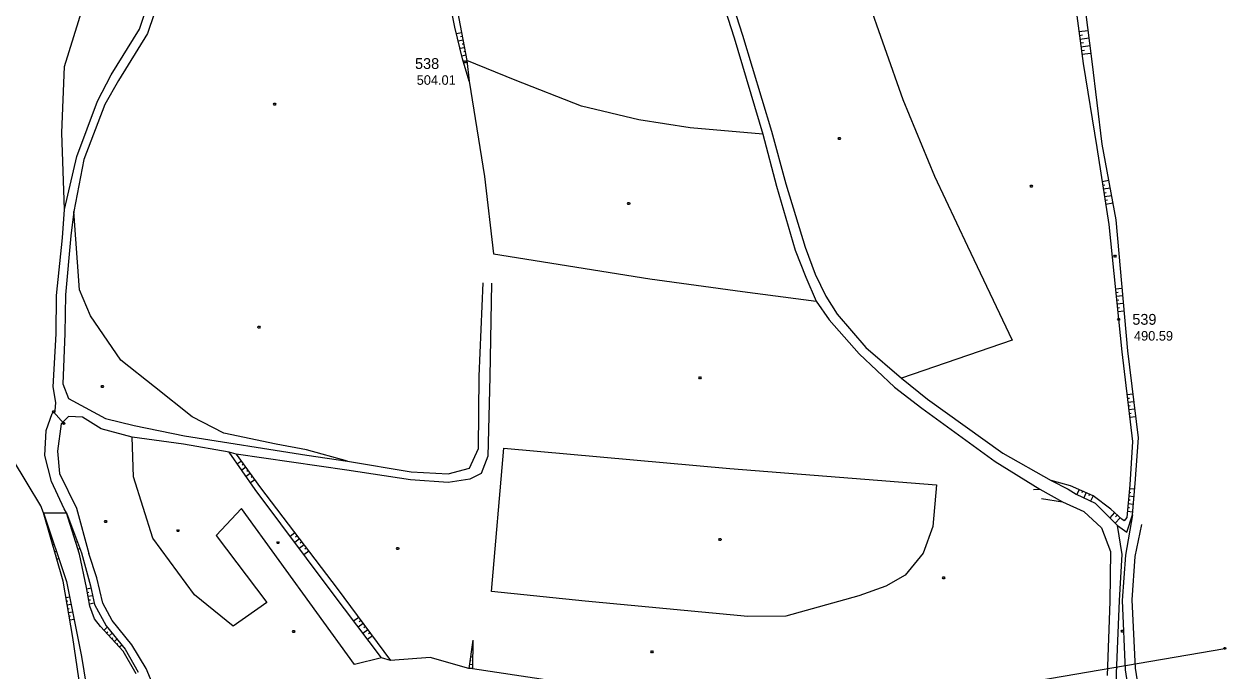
# Model space of a CAD drawing. Extents: x -664960 to -662754, y -993849 to -991145.
# Drawn here: x -663131.8 to -662753.9, y -992572.6 to -992369.4 of the extents above; entities that cross this region are included whole.
import ezdxf

# ---------------------------------------------------------------- set-up
doc = ezdxf.new("R2010")
doc.units = 0
for name, color, linetype in [('Vrstva 1', 7, 'Continuous'), ('Vrstva 13', 7, 'Continuous'), ('Vrstva 24', 7, 'Continuous'), ('Vrstva 27', 7, 'Continuous'), ('Vrstva 37', 7, 'Continuous'), ('Vrstva 57', 7, 'Continuous'), ('Vrstva 63', 7, 'Continuous'), ('Vrstva 8', 7, 'Continuous')]:
    doc.layers.add(name, color=color, linetype=linetype)

msp = doc.modelspace()

# ---------------------------------------------------------------- linework, layer by layer
at = {"layer": 'Vrstva 13'}
for points in [[(-663052.795, -992394.208), (-663052.615, -992394.508), (-663052.795, -992394.808), (-663053.155, -992394.808), (-663053.335, -992394.508), (-663053.155, -992394.208), (-663052.795, -992394.208)], [(-662875.272, -992405.031), (-662875.092, -992405.331), (-662875.272, -992405.631), (-662875.632, -992405.631), (-662875.812, -992405.331), (-662875.632, -992405.031), (-662875.272, -992405.031)], [(-662814.915, -992419.966), (-662814.735, -992420.266), (-662814.915, -992420.566), (-662815.275, -992420.566), (-662815.455, -992420.266), (-662815.275, -992419.966), (-662814.915, -992419.966)], [(-662941.47, -992425.441), (-662941.29, -992425.741), (-662941.47, -992426.041), (-662941.83, -992426.041), (-662942.01, -992425.741), (-662941.83, -992425.441), (-662941.47, -992425.441)], [(-662788.625, -992441.988), (-662788.445, -992442.288), (-662788.625, -992442.588), (-662788.985, -992442.588), (-662789.165, -992442.288), (-662788.985, -992441.988), (-662788.625, -992441.988)], [(-663057.769, -992464.306), (-663057.589, -992464.606), (-663057.769, -992464.906), (-663058.129, -992464.906), (-663058.309, -992464.606), (-663058.129, -992464.306), (-663057.769, -992464.306)], [(-662919.079, -992480.201), (-662918.899, -992480.501), (-662919.079, -992480.801), (-662919.439, -992480.801), (-662919.619, -992480.501), (-662919.439, -992480.201), (-662919.079, -992480.201)], [(-663106.964, -992482.962), (-663106.784, -992483.262), (-663106.964, -992483.562), (-663107.324, -992483.562), (-663107.504, -992483.262), (-663107.324, -992482.962), (-663106.964, -992482.962)], [(-663105.943, -992525.375), (-663105.763, -992525.675), (-663105.943, -992525.975), (-663106.303, -992525.975), (-663106.483, -992525.675), (-663106.303, -992525.375), (-663105.943, -992525.375)], [(-663083.187, -992528.227), (-663083.007, -992528.527), (-663083.187, -992528.827), (-663083.547, -992528.827), (-663083.727, -992528.527), (-663083.547, -992528.227), (-663083.187, -992528.227)], [(-663051.779, -992531.999), (-663051.599, -992532.299), (-663051.779, -992532.599), (-663052.139, -992532.599), (-663052.319, -992532.299), (-663052.139, -992531.999), (-663051.779, -992531.999)], [(-663014.102, -992533.84), (-663013.922, -992534.14), (-663014.102, -992534.44), (-663014.462, -992534.44), (-663014.642, -992534.14), (-663014.462, -992533.84), (-663014.102, -992533.84)], [(-662912.752, -992530.978), (-662912.572, -992531.278), (-662912.752, -992531.578), (-662913.112, -992531.578), (-662913.292, -992531.278), (-662913.112, -992530.978), (-662912.752, -992530.978)], [(-663046.817, -992559.864), (-663046.637, -992560.164), (-663046.817, -992560.464), (-663047.177, -992560.464), (-663047.357, -992560.164), (-663047.177, -992559.864), (-663046.817, -992559.864)], [(-662934.169, -992566.322), (-662933.989, -992566.622), (-662934.169, -992566.922), (-662934.529, -992566.922), (-662934.709, -992566.622), (-662934.529, -992566.322), (-662934.169, -992566.322)]]:
    msp.add_lwpolyline(points, dxfattribs=at)
at = {"layer": 'Vrstva 24'}
msp.add_line((-663122.48, -992491.2), (-663119.31, -992494.83), dxfattribs=at)
for points in [[(-663122.136, -992491.138), (-663122.243, -992491.471), (-663122.588, -992491.533), (-663122.824, -992491.262), (-663122.717, -992490.929), (-663122.372, -992490.867), (-663122.136, -992491.138)], [(-663118.966, -992494.768), (-663119.073, -992495.101), (-663119.418, -992495.163), (-663119.654, -992494.892), (-663119.547, -992494.559), (-663119.202, -992494.497), (-663118.966, -992494.768)]]:
    msp.add_lwpolyline(points, dxfattribs=at)
at = {"layer": 'Vrstva 27'}
for p, q in [((-662814.36, -992515.61), (-662812.41, -992515.53)), ((-662811.92, -992518.37), (-662805.32, -992519.43))]:
    msp.add_line(p, q, dxfattribs=at)
for points in [[(-662962.44, -992285.29), (-662960.53, -992287.98), (-662957.278, -992291.341), (-662954.15, -992294.72), (-662938.36, -992310.24), (-662929.08, -992320.03), (-662920.86, -992330.7), (-662912.84, -992351.32), (-662905.9, -992372.83), (-662896.75, -992402.99), (-662892.28, -992419.6), (-662886.17, -992439.46), (-662883.07, -992447.93), (-662879.65, -992454.82), (-662876.1, -992460.53), (-662867.14, -992470.96), (-662855.91, -992480.61), (-662847.69, -992487.2), (-662824.02, -992504.16), (-662808.83, -992512.81)], [(-662915.46, -992352.13), (-662908.55, -992373.66), (-662899.47, -992403.95), (-662895.23, -992420.32), (-662889.3, -992440.46), (-662885.94, -992448.86), (-662882.7, -992456.39), (-662878.63, -992462.26), (-662869.22, -992472.97), (-662858.13, -992483.47), (-662849.47, -992490.05), (-662826.45, -992506.77), (-662812.41, -992515.53), (-662805.32, -992519.43), (-662798.62, -992522.51), (-662792.97, -992527.59), (-662790.18, -992535.09), (-662790.37, -992550.8), (-662791.29, -992573.99)], [(-663118.46, -992522.94), (-663119.14, -992521.62), (-663123.2, -992513.12), (-663125.3, -992504.94), (-663124.86, -992497.07), (-663122.93, -992491.73), (-663121.97, -992490.9), (-663121.76, -992488.25), (-663122.62, -992483.39), (-663121.64, -992466.72), (-663121.59, -992454.65), (-663119.7, -992436.52), (-663119.1, -992427.6), (-663115.21, -992410.98), (-663108.68, -992393.65), (-663104.35, -992385.29), (-663095.49, -992371.02), (-663091.69, -992359.65)], [(-663088.9, -992360.19), (-663092.97, -992372.36), (-663102.14, -992387.15), (-663106.34, -992394.7), (-663113.04, -992411.93), (-663116.16, -992428.31), (-663117.11, -992435.92), (-663118.74, -992454.46), (-663119.01, -992466.58), (-663119.63, -992482.42), (-663117.8, -992487.01), (-663112.58, -992489.8), (-663106.21, -992493.25), (-663097.17, -992495.53), (-663081.3, -992498.71), (-663042.91, -992504.81), (-663030.1, -992506.69), (-663010.06, -992510.04), (-662998.46, -992510.71), (-662991.72, -992508.85), (-662988.9, -992502.7), (-662988.66, -992479.99), (-662987.44, -992450.67)], [(-662984.85, -992450.76), (-662985.33, -992480.16), (-662985.96, -992505.11), (-662988.05, -992510.57), (-662991.59, -992512.36), (-662998.47, -992513.41), (-663010.23, -992512.59), (-663030.34, -992509.54), (-663065.05, -992504.46), (-663067.25, -992503.83), (-663081.69, -992501.34), (-663097.79, -992499.15), (-663107.52, -992496.58), (-663113.36, -992492.91), (-663117.8, -992492.65), (-663120.15, -992494.99), (-663121.26, -992503.6), (-663120.65, -992510.56), (-663115.29, -992521.42), (-663111.38, -992535.68)], [(-662783.31, -992523.58), (-662785.46, -992536.18), (-662786.51, -992550.42), (-662785.54, -992572.27), (-662783.94, -992583.1)], [(-662814.02, -992628.77), (-662807.9, -992624.04), (-662800.53, -992615), (-662795.19, -992606.64), (-662791.07, -992598.2), (-662789.03, -992589.4), (-662788.34, -992581.72), (-662788.3, -992573.38), (-662787.39, -992550.45), (-662786.57, -992536.01), (-662787.99, -992526.89)], [(-662773.98, -992603.1), (-662777.38, -992600.19), (-662778.5, -992597.92), (-662779.16, -992594.44), (-662780.59, -992582.88), (-662782.36, -992571.76), (-662783.36, -992550.29), (-662782.46, -992536.59), (-662780.37, -992526.63)], [(-663018.16, -992685.44), (-663025.79, -992675.92), (-663035.27, -992659.28), (-663038.99, -992653.02), (-663043.87, -992645.7), (-663048.47, -992640.36), (-663053.15, -992637.16), (-663070.22, -992627.63), (-663076.51, -992622.16), (-663079.98, -992619.34), (-663083.32, -992614.59), (-663086.51, -992609.81), (-663087.86, -992602.34), (-663087.8, -992594.56), (-663088.03, -992588.91), (-663090.1, -992579.58), (-663093.42, -992571.81), (-663097.88, -992564.38), (-663104.09, -992556.79), (-663107.01, -992551.26), (-663108.93, -992543.34), (-663111.38, -992535.68)]]:
    msp.add_lwpolyline(points, dxfattribs=at)
at = {"layer": 'Vrstva 37'}
msp.add_lwpolyline([(-662754.07, -992565.19), (-662753.89, -992565.49), (-662754.07, -992565.79), (-662754.43, -992565.79), (-662754.61, -992565.49), (-662754.43, -992565.19), (-662754.07, -992565.19)], dxfattribs=at)
at = {"layer": 'Vrstva 57'}
msp.add_lwpolyline([(-663665.051, -992722.016), (-663550.65, -992702.35), (-663440.01, -992683.39), (-663326.32, -992663.75), (-663217.09, -992644.97), (-663109.78, -992626.53), (-662986.28, -992605.36), (-662863.82, -992584.32), (-662754.25, -992565.49)], dxfattribs=at)
at = {"layer": 'Vrstva 63'}
for p, q in [((-662800.134, -992371.749), (-662797.222, -992371.366)), ((-662994.263, -992372.117), (-662995.804, -992372.411)), ((-662993.814, -992374.475), (-662995.239, -992374.747)), ((-662994.039, -992373.296), (-662994.532, -992373.39)), ((-662799.978, -992372.939), (-662799.011, -992372.812)), ((-662799.822, -992374.128), (-662796.923, -992373.748)), ((-662799.666, -992375.318), (-662798.703, -992375.192)), ((-662993.365, -992376.832), (-662994.674, -992377.082)), ((-662993.589, -992375.654), (-662994.044, -992375.74)), ((-662993.14, -992378.011), (-662993.556, -992378.091)), ((-662799.51, -992376.508), (-662796.624, -992376.129)), ((-662799.353, -992377.698), (-662798.395, -992377.572)), ((-662799.197, -992378.888), (-662796.325, -992378.51)), ((-662992.915, -992379.19), (-662994.108, -992379.418)), ((-662792.845, -992418.803), (-662790.668, -992418.464)), ((-662792.661, -992419.989), (-662791.924, -992419.874)), ((-662792.476, -992421.175), (-662790.23, -992420.825)), ((-662792.291, -992422.36), (-662791.532, -992422.242)), ((-662792.107, -992423.546), (-662789.792, -992423.185)), ((-662791.922, -992424.732), (-662791.14, -992424.61)), ((-662791.737, -992425.917), (-662789.354, -992425.546)), ((-662788.656, -992452.524), (-662786.477, -992452.299)), ((-662788.532, -992453.718), (-662787.813, -992453.643)), ((-662788.409, -992454.911), (-662786.266, -992454.69)), ((-662788.286, -992456.105), (-662787.578, -992456.032)), ((-662788.163, -992457.299), (-662786.056, -992457.081)), ((-662788.04, -992458.492), (-662787.344, -992458.42)), ((-662787.917, -992459.686), (-662785.845, -992459.472)), ((-662785.04, -992485.745), (-662783.114, -992485.519)), ((-662784.9, -992486.936), (-662784.258, -992486.861)), ((-662784.76, -992488.128), (-662782.827, -992487.902)), ((-662784.621, -992489.32), (-662783.976, -992489.244)), ((-662784.481, -992490.512), (-662782.54, -992490.284)), ((-662784.341, -992491.704), (-662783.694, -992491.628)), ((-662784.201, -992492.896), (-662782.253, -992492.667)), ((-663063.451, -992506.681), (-663064.666, -992507.556)), ((-663062.049, -992508.629), (-663063.297, -992509.528)), ((-663062.75, -992507.655), (-663063.16, -992507.95)), ((-663060.646, -992510.576), (-663061.929, -992511.5)), ((-663061.348, -992509.603), (-663061.769, -992509.906)), ((-663059.244, -992512.524), (-663060.561, -992513.472)), ((-663059.945, -992511.55), (-663060.378, -992511.862)), ((-662800.05, -992515.587), (-662800.748, -992517.143)), ((-662798.955, -992516.078), (-662799.193, -992516.607)), ((-662797.86, -992516.568), (-662798.588, -992518.193)), ((-662796.765, -992517.059), (-662797.013, -992517.612)), ((-662795.67, -992517.55), (-662796.429, -992519.244)), ((-662784.566, -992518.83), (-662784.018, -992518.879)), ((-662784.457, -992517.634), (-662782.818, -992517.783)), ((-662784.349, -992516.439), (-662783.805, -992516.489)), ((-662784.24, -992515.244), (-662782.615, -992515.392)), ((-662784.892, -992522.415), (-662783.224, -992522.566)), ((-662784.783, -992521.22), (-662784.23, -992521.27)), ((-662784.674, -992520.025), (-662783.021, -992520.175)), ((-663125.7, -992522.95), (-663118.46, -992522.94)), ((-662788.956, -992522.835), (-662790.445, -992524.46)), ((-662787.187, -992524.457), (-662788.738, -992526.149)), ((-662788.072, -992523.646), (-662788.578, -992524.198)), ((-663117.014, -992527.459), (-663116.779, -992527.383)), ((-663116.649, -992528.601), (-663116.55, -992528.57)), ((-663116.283, -992529.744), (-663115.928, -992529.631)), ((-663046.629, -992529.199), (-663048.11, -992530.329)), ((-663045.901, -992530.153), (-663046.398, -992530.532)), ((-662787.99, -992526.89), (-662785.01, -992529.04)), ((-663123.485, -992530.545), (-663123.184, -992530.457)), ((-663123.15, -992531.697), (-663123.034, -992531.663)), ((-663122.814, -992532.849), (-663122.42, -992532.734)), ((-663122.478, -992534.001), (-663122.332, -992533.958)), ((-663115.917, -992530.887), (-663115.779, -992530.843)), ((-663115.552, -992532.03), (-663115.078, -992531.879)), ((-663115.186, -992533.173), (-663115.008, -992533.116)), ((-663045.173, -992531.107), (-663046.676, -992532.254)), ((-663043.717, -992533.015), (-663045.242, -992534.178)), ((-663044.445, -992532.061), (-663044.949, -992532.445)), ((-663042.989, -992533.969), (-663043.501, -992534.359)), ((-663122.142, -992535.153), (-663121.657, -992535.012)), ((-663121.806, -992536.305), (-663121.629, -992536.253)), ((-663121.47, -992537.457), (-663120.894, -992537.289)), ((-663114.82, -992534.316), (-663114.227, -992534.126)), ((-663042.261, -992534.923), (-663043.808, -992536.103)), ((-663112.061, -992546.752), (-663110.734, -992546.513)), ((-663111.849, -992547.933), (-663111.393, -992547.851)), ((-663111.637, -992549.114), (-663110.228, -992548.861)), ((-663118.59, -992549.487), (-663117.503, -992549.303)), ((-663118.39, -992550.671), (-663118.015, -992550.607)), ((-663118.19, -992551.854), (-663117.023, -992551.656)), ((-663111.424, -992550.295), (-663110.942, -992550.208)), ((-663111.212, -992551.476), (-663109.722, -992551.208)), ((-663117.989, -992553.037), (-663117.588, -992552.969)), ((-663117.789, -992554.22), (-663116.544, -992554.009)), ((-663117.589, -992555.403), (-663117.161, -992555.331)), ((-663117.388, -992556.586), (-663116.064, -992556.362)), ((-663026.554, -992555.78), (-663028.15, -992556.962)), ((-663106.622, -992559.756), (-663105.609, -992558.829)), ((-663105.812, -992560.641), (-663105.493, -992560.349)), ((-663025.126, -992557.709), (-663026.7, -992558.874)), ((-663025.84, -992556.744), (-663026.368, -992557.135)), ((-663023.698, -992559.638), (-663025.25, -992560.787)), ((-663024.412, -992558.673), (-663024.932, -992559.059)), ((-663105.001, -992561.526), (-663104.097, -992560.698)), ((-663104.19, -992562.411), (-663103.908, -992562.152)), ((-663103.38, -992563.296), (-663102.585, -992562.568)), ((-663102.569, -992564.181), (-663102.323, -992563.955)), ((-663022.27, -992561.567), (-663023.8, -992562.699)), ((-663022.984, -992560.602), (-663023.497, -992560.982)), ((-662990.65, -992562.89), (-662991.98, -992571.79)), ((-662990.65, -992562.89), (-662990.76, -992571.78)), ((-662990.711, -992563.3), (-662990.655, -992563.308)), ((-663101.759, -992565.065), (-663101.073, -992564.438)), ((-662991.243, -992566.86), (-662991.062, -992566.887)), ((-662991.066, -992565.674), (-662990.685, -992565.731)), ((-662990.889, -992564.487), (-662990.816, -992564.498)), ((-662991.775, -992570.421), (-662990.745, -992570.575)), ((-662991.598, -992569.234), (-662991.309, -992569.277)), ((-662991.421, -992568.047), (-662990.715, -992568.153))]:
    msp.add_line(p, q, dxfattribs=at)
for points in [[(-663119.1, -992427.6), (-663119.91, -992403.54), (-663119.07, -992382.76), (-663111.72, -992359.02), (-663111.56, -992348.76), (-663110.23, -992331.66), (-663112.94, -992314.42), (-663119.22, -992303.97), (-663124.27, -992288.96), (-663107.31, -992287.87)], [(-663005.05, -992302.63), (-663003.66, -992317.92), (-663001.97, -992331.54), (-662994.69, -992369.88), (-662992.61, -992380.79)], [(-662991.84, -992387.34), (-662993.89, -992380.32), (-662996.31, -992370.32), (-662998.27, -992360.93), (-662998.3, -992358.91), (-663003, -992332.32), (-663003.1, -992331.06), (-663005.02, -992317.34), (-663005.05, -992302.63)], [(-662875.36, -992328.35), (-662874.09, -992335.77), (-662866.97, -992360.3), (-662855.48, -992393.08), (-662845.48, -992417.13), (-662835.18, -992439.2), (-662821.14, -992468.7), (-662855.91, -992480.61)], [(-662802.05, -992330.2), (-662804.01, -992342.23), (-662798.82, -992381.76), (-662794.5, -992408.18), (-662790.74, -992432.32), (-662786.61, -992472.35), (-662783.31, -992500.5), (-662784.14, -992514.14), (-662785.07, -992524.38), (-662785.85, -992525.39), (-662786.66, -992524.94), (-662790.13, -992521.76), (-662795.67, -992517.55), (-662802.72, -992514.39), (-662808.83, -992512.81), (-662803.49, -992515.44), (-662801, -992517.02), (-662795.02, -992519.93), (-662787.99, -992526.89)], [(-662785.01, -992529.04), (-662783.31, -992523.58), (-662782.47, -992513.69), (-662781.44, -992499.41), (-662784.74, -992472.03), (-662788.36, -992430.9), (-662792.77, -992407.14), (-662796, -992381.1), (-662800.86, -992342.38), (-662798.39, -992334.94)], [(-662899.47, -992403.95), (-662922.31, -992402.03), (-662938.44, -992399.44), (-662956.53, -992395.19), (-662977.41, -992387.01), (-662992.61, -992380.79), (-662991.84, -992387.34), (-662986.97, -992417.22), (-662984.19, -992441.54), (-662935.05, -992449.4), (-662905.88, -992453.4), (-662882.7, -992456.39)], [(-663125.7, -992522.95), (-663126.5, -992520.73), (-663135.09, -992506.52), (-663134.6, -992491.67), (-663141.11, -992493.05), (-663146.95, -992491.13), (-663146.44, -992483.47), (-663138.21, -992475.77), (-663139.42, -992467.43), (-663141.6, -992461.31), (-663148.26, -992456.54), (-663158.14, -992444.66), (-663158.22, -992437.59), (-663163.14, -992428.35), (-663161.52, -992421.55), (-663151.04, -992403.91), (-663153.25, -992386.13), (-663174.26, -992388.31), (-663187.22, -992389.65)], [(-663030.1, -992506.69), (-663042.96, -992503.1), (-663052.5, -992501.39), (-663068.94, -992497.85), (-663078.95, -992492.77), (-663090.72, -992483.33), (-663101.33, -992474.99), (-663110.9, -992461.07), (-663114.3, -992452.89), (-663116.16, -992428.31)], [(-662990.76, -992571.78), (-662991.98, -992571.79), (-663004.09, -992568.36), (-663016.53, -992569.32), (-663019.44, -992568.45), (-663027.87, -992570.59), (-663063.45, -992521.58), (-663071.36, -992530.01), (-663055.44, -992551.08), (-663066.06, -992558.56), (-663078.21, -992548.73), (-663091.34, -992530.86), (-663097.32, -992511.62), (-663097.79, -992499.15)], [(-662980.94, -992502.64), (-662909.84, -992508.99), (-662844.95, -992514.16), (-662846.01, -992527.18), (-662849.04, -992535.55), (-662854.8, -992542.52), (-662860.81, -992545.96), (-662869.37, -992548.96), (-662892.22, -992555.39), (-662904.18, -992555.51), (-662955.37, -992550.65), (-662984.81, -992547.6), (-662980.94, -992502.64)], [(-663019.44, -992568.45), (-663034.96, -992547.98), (-663059.12, -992515.55), (-663067.25, -992503.83)], [(-663065.05, -992504.46), (-663057.44, -992515.03), (-663033.29, -992546.68), (-663016.53, -992569.32)], [(-663125.7, -992522.95), (-663118.49, -992544.46), (-663113.69, -992568.01), (-663111.51, -992581.53), (-663110.84, -992595.54), (-663109.76, -992615.3), (-663106.07, -992623.94), (-663101.92, -992630.8), (-663099.58, -992637.28), (-663097.5, -992647.26), (-663101.43, -992657.15), (-663107.33, -992676.63), (-663112.78, -992701.15), (-663115.39, -992714), (-663120.22, -992737.13), (-663124.22, -992747.58), (-663121.6, -992737.04), (-663116.85, -992713.64), (-663114.04, -992700.92), (-663108.41, -992676.42), (-663104.77, -992656.55), (-663103.01, -992644.07), (-663105.02, -992635.07), (-663110.57, -992625.46)], [(-663110.57, -992625.46), (-663115.56, -992616.26), (-663112.54, -992597.09), (-663113.62, -992581.3), (-663116.46, -992562.07), (-663119.46, -992544.35), (-663125.7, -992522.95)], [(-663118.46, -992522.94), (-663113.7, -992535.52), (-663110.87, -992545.88), (-663109.61, -992551.73), (-663105.94, -992558.42), (-663099.98, -992565.79), (-663095.86, -992573.01)], [(-663096.52, -992573.47), (-663100.6, -992566.33), (-663107.7, -992558.58), (-663109.68, -992556.24), (-663111.08, -992552.21), (-663112.13, -992546.37), (-663114.32, -992535.88), (-663118.46, -992522.94)], [(-662842.44, -992543.02), (-662842.26, -992543.32), (-662842.44, -992543.62), (-662842.8, -992543.62), (-662842.98, -992543.32), (-662842.8, -992543.02), (-662842.44, -992543.02)], [(-662786.28, -992559.78), (-662786.1, -992560.08), (-662786.28, -992560.38), (-662786.64, -992560.38), (-662786.82, -992560.08), (-662786.64, -992559.78), (-662786.28, -992559.78)], [(-662990.76, -992571.78), (-662958.07, -992576.73), (-662942, -992578.62), (-662919.89, -992581.4)]]:
    msp.add_lwpolyline(points, dxfattribs=at)
at = {"layer": 'Vrstva 8'}
for points in [[(-662992.96, -992380.97), (-662992.78, -992381.27), (-662992.96, -992381.57), (-662993.32, -992381.57), (-662993.5, -992381.27), (-662993.32, -992380.97), (-662992.96, -992380.97)], [(-662787.43, -992461.83), (-662787.25, -992462.13), (-662787.43, -992462.43), (-662787.79, -992462.43), (-662787.97, -992462.13), (-662787.79, -992461.83), (-662787.43, -992461.83)]]:
    msp.add_lwpolyline(points, dxfattribs=at)

# ---------------------------------------------------------------- texts
at = {"layer": 'Vrstva 1'}
for s, p in [('538', (-663008.853, -992383.484)), ('539', (-662783.332, -992463.846))]:
    msp.add_text(s, height=3.4, dxfattribs=at).set_placement(p)
at = {"layer": 'Vrstva 63'}
for s, p in [('504.01', (-663008.329, -992388.464)), ('490.59', (-662782.808, -992468.826))]:
    msp.add_text(s, height=3, dxfattribs=at).set_placement(p)

doc.saveas('drawing.dxf')
